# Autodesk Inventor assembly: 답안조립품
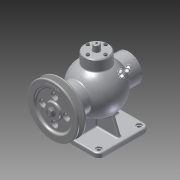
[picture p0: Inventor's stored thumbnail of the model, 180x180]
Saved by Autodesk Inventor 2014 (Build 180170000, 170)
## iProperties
Created: 2015-10
Part Number: 답안조립품
Document SubType Name: Assembly
Designer: youjin20
Author: youjin20
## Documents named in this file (19)
- C:\Users\youjin20\Desktop\451010V1016\답안조립품.iam
- C:\Users\youjin20\Desktop\451010V1016\본체.ipt
- C:\Users\youjin20\Desktop\451010V1016\뒤커버.ipt
- C:\Users\youjin20\Desktop\451010V1016\앞커버.ipt
- C:\Users\youjin20\Desktop\451010V1016\상부커버.ipt
- C:\Users\youjin20\Desktop\451010V1016\볼트 M 4 x 12.ipt
- C:\Users\youjin20\Desktop\451010V1016\볼트 M4 x 16.ipt
- C:\Users\youjin20\Desktop\451010V1016\오일실 15 30 7.ipt
- C:\Users\youjin20\Desktop\451010V1016\베어링- 6202.ipt
- KS B 2023 - 6202 - 15 x 35 x 11 - 7.8.ipt
- C:\Users\youjin20\Desktop\451010V1016\부시.ipt
- C:\Users\youjin20\Desktop\451010V1016\편심축.ipt
- C:\Users\youjin20\Desktop\451010V1016\멈춤링- 15 x 1.ipt
- C:\Users\youjin20\Desktop\451010V1016\멈춤링- 35x1.6.ipt
- KS B 1336 - 35x1.6.ipt
- C:\Users\youjin20\Desktop\451010V1016\V-벨트풀리.ipt
- C:\Users\youjin20\Desktop\451010V1016\키 4 x 4 x 12.ipt
- C:\Users\youjin20\Desktop\451010V1016\너트 M8.ipt
- C:\Users\youjin20\Desktop\451010V1016\슬라이드.ipt
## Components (16 placed, 5 different names)
1. KS B 2023 - 6202 - 15 x 35 x 11 - 7.8:1 — Mate:12, Mate:13, Angle:2
2. KS B 2023 - 6202 - 15 x 35 x 11 - 7.8:2 — Mate:14, Mate:15, Mate:16, Mate:17, Angle:1
3. KS B 1336 - 35x1.6:1 — Mate:22, Mate:23
4. V-벨트풀리:1 — Mate:27, Mate:28, Mate:29, Mate:31
5. KS B 1021 - 에 따름 ISO 1207 - 미터 A  M 4 x 12:1 — Insert:1
6. KS B 1021 - 에 따름 ISO 1207 - 미터 A  M 4 x 12:2
7. KS B 1021 - 에 따름 ISO 1207 - 미터 A  M 4 x 12:3
8. KS B 1021 - 에 따름 ISO 1207 - 미터 A  M 4 x 12:4
9. ISO 4762 M4 x 16:2 — Insert:3
10. ISO 4762 M4 x 16:3
11. ISO 4762 M4 x 16:4
12. ISO 4762 M4 x 16:5
13. ISO 4762 M4 x 16:1 — Insert:2
14. ISO 4762 M4 x 16:6
15. ISO 4762 M4 x 16:7
16. ISO 4762 M4 x 16:8
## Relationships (17: Mate 12, Insert 3, Angle 2)
- Insert:1: KS B 1021 - 에 따름 ISO 1207 - 미터 A  M 4 x 12:1
- Insert:2: ISO 4762 M4 x 16:1
- Insert:3: ISO 4762 M4 x 16:2
- Mate:12: KS B 2023 - 6202 - 15 x 35 x 11 - 7.8:1
- Mate:13: KS B 2023 - 6202 - 15 x 35 x 11 - 7.8:1
- Mate:14: KS B 2023 - 6202 - 15 x 35 x 11 - 7.8:2
- Mate:15: KS B 2023 - 6202 - 15 x 35 x 11 - 7.8:2
- Mate:16: KS B 2023 - 6202 - 15 x 35 x 11 - 7.8:2
- Mate:17: KS B 2023 - 6202 - 15 x 35 x 11 - 7.8:2
- Mate:22: KS B 1336 - 35x1.6:1
- Mate:23: KS B 1336 - 35x1.6:1
- Mate:27: V-벨트풀리:1
- Mate:28: V-벨트풀리:1
- Mate:29: V-벨트풀리:1
- Mate:31: V-벨트풀리:1
- Angle:1: KS B 2023 - 6202 - 15 x 35 x 11 - 7.8:2
- Angle:2: KS B 2023 - 6202 - 15 x 35 x 11 - 7.8:1
